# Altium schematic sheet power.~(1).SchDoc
size A3
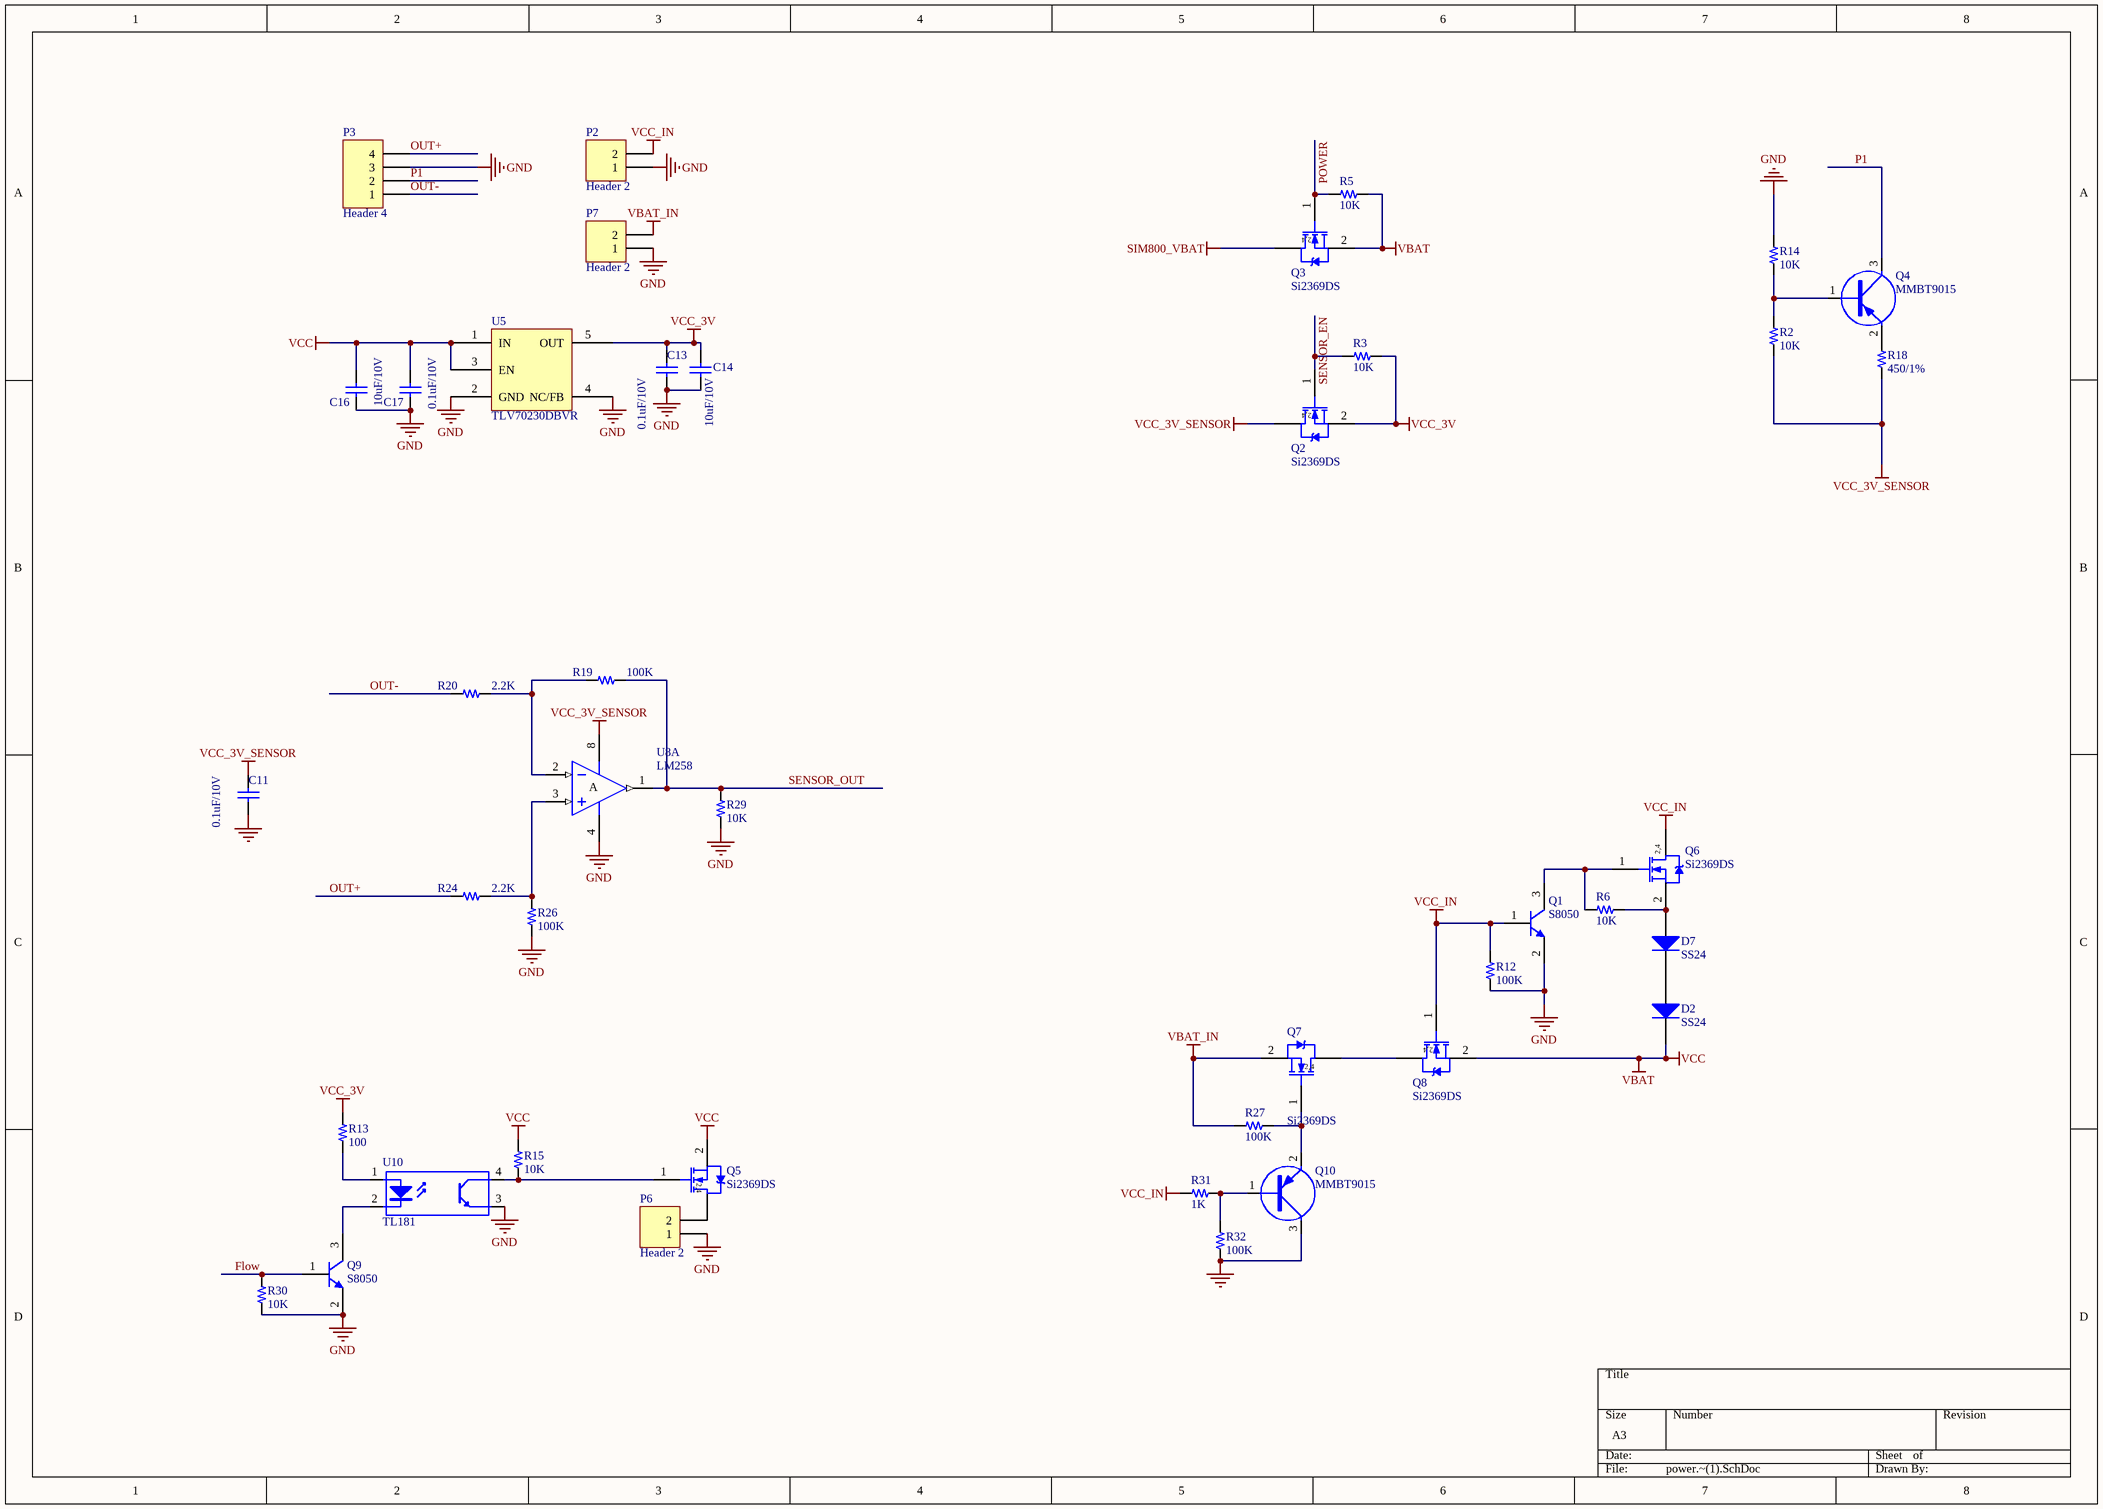
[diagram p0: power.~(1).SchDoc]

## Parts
C11  0.1uF/10V  [0603C]
C13  0.1uF/10V  [0603C]
C14  10uF/10V  [0603C]
C16  10uF/10V  [0603C]
C17  0.1uF/10V  [0603C]
D2  SS24  [SMA]
D7  SS24  [SMA]
P2  Header 2  [2X2.54MM]
P3  Header 4  [HDR1X4]
P6  Header 2  [HDR1X2]
P7  Header 2  [2X2.54MM]
Q1  S8050  [SOT23-3]
Q2  Si2369DS  [SOT23-3]
Q3  Si2369DS  [SOT23-3]
Q4  MMBT9015  [SOT23-3]
Q5  Si2369DS  [SOT23-3]
Q6  Si2369DS  [SOT23-3]
Q7  Si2369DS  [SOT23-3]
Q8  Si2369DS  [SOT23-3]
Q9  S8050  [SOT23-3]
Q10  MMBT9015  [SOT23-3]
R2  10K  [0603R]
R3  10K  [0603R]
R5  10K  [0603R]
R6  10K  [0603R]
R12  100K  [0603R]
R13  100  [0603R]
R14  10K  [0603R]
R15  10K  [0603R]
R18  450/1%  [0603R]
R19  100K  [0603R]
R20  2.2K  [0603R]
R24  2.2K  [0603R]
R26  100K  [0603R]
R27  100K  [0603R]
R29  10K  [0603R]
R30  10K  [0603R]
R31  1K  [0603R]
R32  100K  [0603R]
U5  TLV70230DBVR  [SOT23-5(DBV)]
U8  LM258  [so-8]  (part A of 2)
U10  TL181  [DIP-4]

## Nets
GND: C11.2 C13.2 C14.1 C16.1 C17.2 P2.1 P3.3 P6.1 P7.1 Q1.2(E) Q9.2(E) Q10.3(C) R12.2 R14.2 R26.1 R29.1 R30.1 R32.1 U5.2(GND) U5.4(NC/FB) U8.4(V-) U10.3(E)
SIM800_VBAT: Q3.3(D)
VBAT: C16.2 C17.1 D2.2(K) Q3.2(S) Q5.2(S) Q8.2(S) R5.1 R15.2 U5.1(IN) U5.3(EN)  [also labelled VCC]
VBAT_IN: P7.2 Q7.2(S) R27.1
VCC_3V: C13.1 C14.2 Q2.2(S) R3.1 R13.2 U5.5(OUT)
VCC_3V_SENSOR: C11.1 Q2.3(D) R2.1 R18.1 U8.8(V+)
VCC_IN: P2.2 Q1.1(B) Q6.3(D) Q8.1(G) R12.1 R31.1
Flow: Q9.1(B) R30.2
OUT+: P3.4 R24.1
OUT-: P3.1 R20.1
P1: P3.2 Q4.3(C)
POWER: Q3.1(G) R5.2
SENSOR_EN: Q2.1(G) R3.2
SENSOR_OUT: R19.2 R29.2 U8.1(OUT)
NetD2_1: D2.1(A) D7.2(K)
NetD7_1: D7.1(A) Q6.2(S) R6.1
NetP6_2: P6.2 Q5.3(D)
NetQ1_3: Q1.3(C) Q6.1(G) R6.2
NetQ4_1: Q4.1(B) R2.2 R14.1
NetQ4_2: Q4.2(E) R18.2
NetQ5_1: Q5.1(G) R15.1 U10.4(C)
NetQ7_1: Q7.1(G) Q10.2(E) R27.2
NetQ7_3: Q7.3(D) Q8.3(D)
NetQ9_3: Q9.3(C) U10.2(K)
NetQ10_1: Q10.1(B) R31.2 R32.2
NetR13_1: R13.1 U10.1(A)
NetR19_1: R19.1 R20.2 U8.2(IN-)
NetR24_2: R24.2 R26.2 U8.3(IN+)

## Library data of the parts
C11 C13 C17 = Cap: Capacitor; Value: 104
C14 = Cap: Capacitor
C16 = Cap: Capacitor; Value: 106/50V
D2 D7 = Diode 1N4148: High Conductance Fast Diode
P2 P6 P7 = Header 2: Header, 2-Pin
P3 = Header 4: Header, 4-Pin
Q1 Q9 = NPN
Q2 Q3 Q5-Q8 = BUK92150-55A
Q4 Q10 = PNP
R2 R3 R5 R6 R12-R15 R18-R20 R24 R26 R27 R29-R32 = R
U10 = Optoisolator1: 4-Pin Phototransistor Optocoupler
